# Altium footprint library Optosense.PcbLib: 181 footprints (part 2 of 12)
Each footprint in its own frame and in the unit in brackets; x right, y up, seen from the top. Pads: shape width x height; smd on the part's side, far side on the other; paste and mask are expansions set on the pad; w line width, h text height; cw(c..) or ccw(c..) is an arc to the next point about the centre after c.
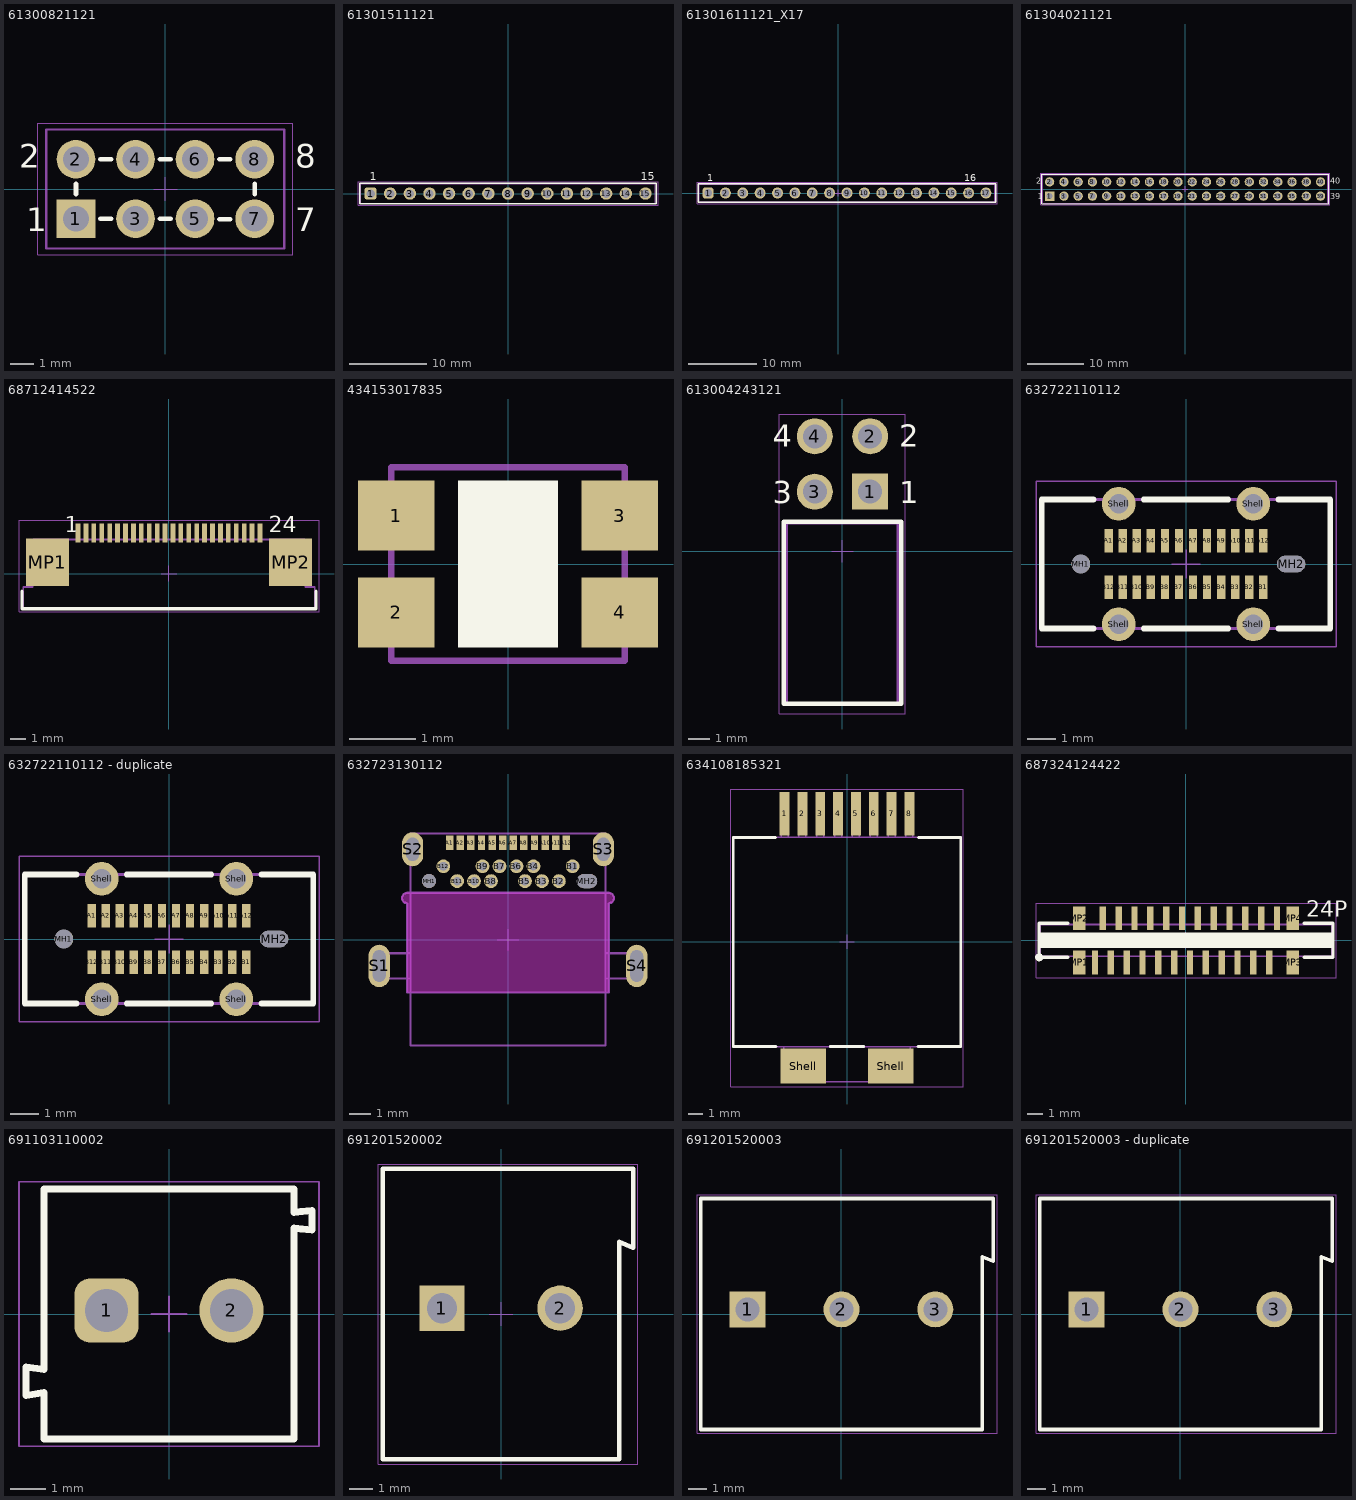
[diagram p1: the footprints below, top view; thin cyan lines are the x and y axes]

## 61300821121 [mm] "Pin Header, pitch 2.54 mm, THT, Vertical, dual row, 8p"
height 8.54
pads (8):
  rect 1.65x1.65 hole 1.1: 1(-3.81,-1.27)
  round 1.65 hole 1.1: 2(-3.81,1.27) 3(-1.27,-1.27) 4(-1.27,1.27) 5(1.27,-1.27) 6(1.27,1.27) 7(3.81,-1.27) 8(3.81,1.27)
Top Overlay:
  lines w0.2: -3.81,-0.229 -3.81,0.229 ; -2.769,-1.27 -2.311,-1.27 ; -2.769,1.27 -2.311,1.27 ; -0.229,-1.27 0.229,-1.27 ; -0.229,1.27 0.229,1.27 ; 2.311,-1.295 2.769,-1.295 ; 2.311,1.27 2.769,1.27 ; 3.81,-0.229 3.81,0.229
  text "8" at 5.54,0.9 h1.02
  text "7" at 5.54,-1.8 h1.02
  text "2" at -6.24,0.9 h1.02
  text "1" at -5.94,-1.8 h1.02
Mechanical 13:
  lines w0.1: -5.08,-2.54 5.08,-2.54 5.08,2.54 -5.08,2.54 -5.08,-2.54
Mechanical 15:
  lines w0.05: -0.5,0 0.5,0 ; 0,-0.5 0,0.5 ; -5.43,-2.815 -5.43,2.815 5.43,2.815 5.43,-2.815 -5.43,-2.815
3D body "61300821121.stp": height 8.59, standoff -2.95, extent -5.08,-2.54 5.08,2.54

## 61301511121 [mm] "Pin Header, pitch 2.54 mm, THT, Vertical, single row, 15p"
height 8.54
pads (15):
  rrect50% 1.6x1.6 hole 1.1: 1(-17.78,0)
  round 1.6 hole 1.1: 2(-15.24,0) 3(-12.7,0) 4(-10.16,0) 5(-7.62,0) 6(-5.08,0) 7(-2.54,0) 8(0,0) 9(2.54,0) 10(5.08,0) 11(7.62,0) 12(10.16,0) 13(12.7,0) 14(15.24,0) 15(17.78,0)
Top Overlay:
  lines w0.2: -19.2,-1.345 19.2,-1.345 19.2,1.345 -19.2,1.345 -19.2,-1.345
  text "15" at 17.15,1.7 h1.02
  text "1" at -17.9,1.7 h1.02
Top 3D Body:
  lines w0.1: -19.05,-1.27 -19.05,1.27 19.05,1.27 19.05,-1.27 -19.05,-1.27
Top Courtyard:
  lines w0.05: -0.5,0 0.5,0 ; 0,-0.5 0,0.5 ; -19.4,-1.545 -19.4,1.545 19.4,1.545 19.4,-1.545 -19.4,-1.545
Top Assembly:
  lines w0.1: -19.05,-1.27 -19.05,1.27 19.05,1.27 19.05,-1.27 -19.05,-1.27
  text ".Designator" at -7.498,-0.5 h1.5
3D body "61301511121.stp": height 8.57, standoff -2.97, extent -19.05,-1.27 19.05,1.27

## 61301611121_X17 [mm] "Pin Header, pitch 2.54 mm, THT, Vertical, single row, 16p"
height 8.54
pads (17):
  rrect50% 1.6x1.6 hole 1.1: 1(-19.05,0)
  round 1.6 hole 1.1: 2(-16.51,0) 3(-13.97,0) 4(-11.43,0) 5(-8.89,0) 6(-6.35,0) 7(-3.81,0) 8(-1.27,0) 9(1.27,0) 10(3.81,0) 11(6.35,0) 12(8.89,0) 13(11.43,0) 14(13.97,0) 15(16.51,0) 16(19.05,0) 17(21.59,0)
Top Overlay:
  lines w0.2: -20.47,-1.345 -20.47,1.345 23.01,1.345 23.01,-1.345 -20.47,-1.345
  text "16" at 18.42,1.7 h1.02
  text "1" at -19.17,1.7 h1.02
Top 3D Body:
  lines w0.1: 20.32,-1.27 -20.32,-1.27 -20.32,1.27 20.32,1.27 ; 22.86,-1.27 22.86,1.27
Top Courtyard:
  lines w0.05: -0.5,0 0.5,0 ; 0,-0.5 0,0.5 ; -20.67,-1.545 23.21,-1.545 23.21,1.545 -20.67,1.545 -20.67,-1.545
Top Assembly:
  lines w0.1: -20.32,-1.27 22.86,-1.27 22.86,1.27 -20.32,1.27 -20.32,-1.27
  text ".Designator" at -7.498,-0.5 h1.5
3D body "61301611121.stp": height 8.57, standoff -2.97, extent -17.78,-1.27 22.86,1.27
3D body "61301611121.stp": height 8.57, standoff -2.97, extent -20.32,-1.27 20.32,1.27

## 61304021121 [mm] "Pin Header, pitch 2.54 mm, THT, Vertical, dual row, 40p"
height 8.54
pads (40):
  rect 1.65x1.65 hole 1.1: 1(-24.13,-1.27)
  round 1.65 hole 1.1: 2(-24.13,1.27) 3(-21.59,-1.27) 4(-21.59,1.27) 5(-19.05,-1.27) 6(-19.05,1.27) 7(-16.51,-1.27) 8(-16.51,1.27) 9(-13.97,-1.27) 10(-13.97,1.27) 11(-11.43,-1.27) 12(-11.43,1.27) 13(-8.89,-1.27) 14(-8.89,1.27) 15(-6.35,-1.27) 16(-6.35,1.27) 17(-3.81,-1.27) 18(-3.81,1.27) 19(-1.27,-1.27) 20(-1.27,1.27) 21(1.27,-1.27) 22(1.27,1.27) 23(3.81,-1.27) 24(3.81,1.27) 25(6.35,-1.27) 26(6.35,1.27) 27(8.89,-1.27) 28(8.89,1.27) 29(11.43,-1.27) 30(11.43,1.27) 31(13.97,-1.27) 32(13.97,1.27) 33(16.51,-1.27) 34(16.51,1.27) 35(19.05,-1.27) 36(19.05,1.27) 37(21.59,-1.27) 38(21.59,1.27) 39(24.13,-1.27) 40(24.13,1.27)
Top Overlay:
  lines w0.2: -25.55,-2.615 -25.55,2.615 25.55,2.615 25.55,-2.615 -25.55,-2.615
  text "40" at 25.86,0.9 h1.02
  text "39" at 25.86,-1.8 h1.02
  text "1" at -26.26,-1.8 h1.02
  text "2" at -26.56,0.9 h1.02
Mechanical 13:
  lines w0.1: -25.4,-2.54 -25.4,2.54 25.4,2.54 25.4,-2.54 -25.4,-2.54
Mechanical 15:
  lines w0.05: -0.5,0 0.5,0 ; 0,-0.5 0,0.5 ; -25.75,-2.815 25.75,-2.815 25.75,2.815 -25.75,2.815 -25.75,-2.815
3D body "61304021121.stp": height 8.59, standoff -2.95, extent -25.4,-2.54 25.4,2.54

## 68712414522 [mm] "ZIF Connectors, Horizontal, Bottom Contact, pitch 0.5mm, 24p"
height 2.25
pads (26):
  rect 0.3x1.2 smd: 1(-5.75,2.56) 2(-5.25,2.56) 3(-4.75,2.56) 4(-4.25,2.56) 5(-3.75,2.56) 6(-3.25,2.56) 7(-2.75,2.56) 8(-2.25,2.56) 9(-1.75,2.56) 10(-1.25,2.56) 11(-0.75,2.56) 12(-0.25,2.56) 13(0.25,2.56) 14(0.75,2.56) 15(1.25,2.56) 16(1.75,2.56) 17(2.25,2.56) 18(2.75,2.56) 19(3.25,2.56) 20(3.75,2.56) 21(4.25,2.56) 22(4.75,2.56) 23(5.25,2.56) 24(5.75,2.56)
  rect 2.7x3 smd: MP1(-7.68,0.7) MP2(7.68,0.7)
Top Overlay:
  lines w0.2: -9.275,-1.125 -9.275,-2.225 9.275,-2.225 9.275,-1.125
  text "24" at 6.3,2.61 h1.02
  text "1" at -6.6,2.61 h1.02
Mechanical 13:
  lines w0.1: -9.2,-2.15 -9.2,-0.85 -8.6,-0.85 -8.6,2.15 8.6,2.15 8.6,-0.85 9.2,-0.85 9.2,-2.15 -9.2,-2.15
Mechanical 15:
  lines w0.05: -0.5,0 0.5,0 ; 0,-0.5 0,0.5 ; -9.475,-2.425 9.475,-2.425 9.475,3.36 -9.475,3.36 -9.475,-2.425
3D body "68712414522.stp": height 2.1, standoff 0, extent -9.2,-2.15 9.2,2.95

## 434153017835 [mm] "Tact Switch, SMD, body 3.5x2.9mm"
height 1.7
pads (4):
  rect 1.15x1.05 smd: 1(-1.675,0.725) 2(-1.675,-0.725) 3(1.675,0.725) 4(1.675,-0.725)
Top Overlay:
  rectangle: -0.75,-1.25 0.75,1.25
Mechanical 11:
  lines w0.1: -1.75,-1.45 -1.75,1.45 1.75,1.45 1.75,-1.45 -1.75,-1.45
  text ".Designator" at -1.4,-0.6 h1.2
Mechanical 13:
  lines w0.1: -1.75,-1.45 1.75,-1.45 1.75,1.45 -1.75,1.45 -1.75,-1.45
Mechanical 15:
  lines w0.05: -0.5,0 0.5,0 ; 0,-0.5 0,0.5
3D body "434153017835.stp": height 1.7, standoff 0, extent -2.147,-1.45 2.147,1.45

## 613004243121 [mm]
height 5.08
pads (4):
  rect 1.65x1.65 hole 1.1: 1(1.27,2.73)
  round 1.65 hole 1.1: 2(1.27,5.27) 3(-1.27,2.73) 4(-1.27,5.27)
Top Overlay:
  lines w0.2: -2.69,-7 -2.69,1.345 2.69,1.345 2.69,-7 -2.69,-7
  text "1" at 2.6,2.2 h1.02
  text "2" at 2.6,4.8 h1.02
  text "4" at -3.2,4.8 h1.02
  text "3" at -3.2,2.2 h1.02
Mechanical 13:
  lines w0.1: -2.54,-7 2.54,-7 2.54,1.27 -2.54,1.27 -2.54,-7
Mechanical 15:
  lines w0.05: -0.5,0 0.5,0 ; 0,-0.5 0,0.5 ; -2.89,-7.47 -2.89,6.295 2.89,6.295 2.89,-7.47 -2.89,-7.47
3D body "613004243121.stp": height 5.05, standoff -3.25, extent -2.79,-7.1 2.79,5.5

## 632722110112 [mm] "USB_Type C 3.1_Vertical_SMT_1,0mm"
height 7.6
pads (30):
  rect 0.3x0.85 smd: A1(-2.75,0.83) A2(-2.25,0.83) A3(-1.75,0.83) A4(-1.25,0.83) A5(-0.75,0.83) A6(-0.25,0.83) A7(0.25,0.83) A8(0.75,0.83) A9(1.25,0.83) A10(1.75,0.83) A11(2.25,0.83) A12(2.75,0.83) B1(2.75,-0.83) B2(2.25,-0.83) B3(1.75,-0.83) B4(1.25,-0.83) B5(0.75,-0.83) B6(0.25,-0.83) B7(-0.25,-0.83) B8(-0.75,-0.83) B9(-1.25,-0.83) B10(-1.75,-0.83) B11(-2.25,-0.83) B12(-2.75,-0.83)
  round 0.66 hole 0.66 unplated: MH1(-3.75,0)
  oval 1x0.58 hole 0.58 slot 1 at 0 deg unplated: MH2(3.75,0)
  round 1.2 hole 0.7: Shell(-2.4,-2.15) Shell(-2.4,2.15) Shell(2.4,-2.15) Shell(2.4,2.15)
Top Overlay:
  lines w0.2: -3.3,-2.3 -5.15,-2.3 -5.15,2.3 -3.3,2.3 ; -1.5,-2.3 1.5,-2.3 ; -1.5,2.3 1.5,2.3 ; 3.3,-2.3 5.15,-2.3 5.15,2.3 3.3,2.3
Mechanical 11:
  lines w0.1: -5.15,-2.3 5.15,-2.3 5.15,2.3 -5.15,2.3 -5.15,-2.3
  text ".Designator" at -1.75,-0.75 h1.5
Mechanical 13:
  lines w0.1: -5.15,-2.3 -5.15,2.3 5.15,2.3 5.15,-2.3 -5.15,-2.3
Mechanical 15:
  lines w0.05: -0.5,0 0.5,0 ; 0,-0.5 0,0.5 ; -5.35,-2.95 -5.35,2.95 5.35,2.95 5.35,-2.95 -5.35,-2.95
3D body "632722110112.stp": height 7.95, standoff -1.32, extent -5.15,-2.3 5.15,2.3

## 632722110112 - duplicate [mm] "USB_Type C 3.1_Vertical_SMT_1,0mm"
height 7.6
pads (30):
  rect 0.3x0.85 smd: A1(-2.75,0.83) A2(-2.25,0.83) A3(-1.75,0.83) A4(-1.25,0.83) A5(-0.75,0.83) A6(-0.25,0.83) A7(0.25,0.83) A8(0.75,0.83) A9(1.25,0.83) A10(1.75,0.83) A11(2.25,0.83) A12(2.75,0.83) B1(2.75,-0.83) B2(2.25,-0.83) B3(1.75,-0.83) B4(1.25,-0.83) B5(0.75,-0.83) B6(0.25,-0.83) B7(-0.25,-0.83) B8(-0.75,-0.83) B9(-1.25,-0.83) B10(-1.75,-0.83) B11(-2.25,-0.83) B12(-2.75,-0.83)
  round 0.66 hole 0.66 unplated: MH1(-3.75,0)
  oval 1x0.58 hole 0.58 slot 1 at 0 deg unplated: MH2(3.75,0)
  round 1.2 hole 0.7: Shell(-2.4,-2.15) Shell(-2.4,2.15) Shell(2.4,-2.15) Shell(2.4,2.15)
Top Overlay:
  lines w0.2: -3.3,-2.3 -5.15,-2.3 -5.15,2.3 -3.3,2.3 ; -1.5,-2.3 1.5,-2.3 ; -1.5,2.3 1.5,2.3 ; 3.3,-2.3 5.15,-2.3 5.15,2.3 3.3,2.3
Top 3D Body:
  lines w0.1: -5.15,-2.3 5.15,-2.3 5.15,2.3 -5.15,2.3 -5.15,-2.3
Top Courtyard:
  lines w0.05: -0.5,0 0.5,0 ; 0,-0.5 0,0.5 ; -5.35,-2.95 5.35,-2.95 5.35,2.95 -5.35,2.95 -5.35,-2.95
Top Component Outline:
  lines w0.1: -5.15,-2.3 -5.15,2.3 5.15,2.3 5.15,-2.3 -5.15,-2.3
Top Designator:
  text ".Designator" at -7.498,-0.5 h1.5
3D body "632722110112.stp": height 7.95, standoff -1.32, extent -5.15,-2.3 5.15,2.3

## 632723130112 [mm] "USB_Type C 3.1_Mid-Mount_THR/SMT_1,6mm"
height 3.42
pads (30):
  rect 0.35x0.7 smd: A1(-2.75,4.57) A2(-2.25,4.57) A3(-1.75,4.57) A4(-1.25,4.57) A5(-0.75,4.57) A6(-0.25,4.57) A7(0.25,4.57) A8(0.75,4.57) A9(1.25,4.57) A10(1.75,4.57) A11(2.25,4.57) A12(2.75,4.57)
  round 0.65 hole 0.4: B1(3.05,3.46) B2(2.4,2.76) B3(1.6,2.76) B4(1.2,3.46) B5(0.8,2.76) B6(0.4,3.46) B7(-0.4,3.46) B8(-0.8,2.76) B9(-1.2,3.46) B10(-1.6,2.76) B11(-2.4,2.76) B12(-3.05,3.46)
  round 0.65 hole 0.65 unplated: MH1(-3.725,2.76)
  oval 0.95x0.65 hole 0.65 slot 0.95 at 0 deg unplated: MH2(3.725,2.76)
  oval 1x2 hole 0.6 slot 1.5 at 90 deg: S1(-6.075,-1.24) S4(6.075,-1.24)
  oval 1x1.6 hole 0.6 slot 1.1 at 90 deg: S2(-4.5,4.26) S3(4.5,4.26)
Keep-Out Layer:
  board cut-out: -4.75,-2.49 4.75,-2.49 4.75,1.71 4.8,1.71 4.892,1.748 4.962,1.818 5,1.91 5,2.01 4.962,2.102 4.892,2.172 4.8,2.21 4.75,2.21 -4.75,2.21 -4.8,2.21 -4.892,2.172 -4.962,2.102 -5,2.01 -5,1.91 -4.962,1.818 -4.892,1.748 -4.8,1.71 -4.75,1.71
Mechanical 2:
  lines w0.1: -4.75,-2.49 4.75,-2.49
  text "PCB End" at -1.85,-3.39 h1.02
Mechanical 8:
  lines w0.1: -4.75,-2.49 4.75,-2.49 4.75,1.71 ccw(c4.75,1.96) 4.75,2.21 -4.75,2.21 ccw(c-4.75,1.96) -4.75,1.71 -4.75,-2.49
  text "Milling Area" at -2.2,-0.34 h1.02
Mechanical 13:
  lines w0.1: -4.6,-1.84 -6.175,-1.84 -6.175,-0.64 -4.6,-0.64 ; 4.6,-1.84 6.175,-1.84 6.175,-0.64 4.6,-0.64 ; -4.6,-5 4.6,-5 4.6,5 -4.6,5 -4.6,-5
Mechanical 15:
  lines w0.05: -0.5,0 0.5,0 ; 0,-0.5 0,0.5
3D body "632723130112.stp": height 2.04, standoff -1.56, extent -6.175,-5 6.175,4.994

## 634108185321 [mm] "Modular Jack Vertical Shielded SMT  with Solder Tab 8P8C Top Entry"
height 13.3
pads (10):
  rect 0.7x3.1 smd: 1(-4.445,9.15) 2(-3.175,9.15) 3(-1.905,9.15) 4(-0.635,9.15) 5(0.635,9.15) 6(1.905,9.15) 7(3.175,9.15) 8(4.445,9.15)
  rect 3.25x2.5 smd: Shell(-3.125,-8.85) Shell(3.125,-8.85)
Top Overlay:
  lines w0.2: -5.1,7.45 -8.1,7.45 -8.1,-7.45 -5.05,-7.45 ; -1.2,-7.45 1.2,-7.45 ; 5.05,-7.45 8.1,-7.45 8.1,7.45 5.1,7.45
Top 3D Body:
  lines w0.1: -4.695,7.45 -4.695,9.1 -4.195,9.1 -4.195,7.45 ; -4.5,-7.45 -4.5,-9.95 4.5,-9.95 4.5,-7.45 ; -3.425,7.45 -3.425,9.1 -2.925,9.1 -2.925,7.45 ; -2.155,7.45 -2.155,9.1 -1.655,9.1 -1.655,7.45 ; -0.885,7.45 -0.885,9.1 -0.385,9.1 -0.385,7.45 ; 0.385,7.45 0.385,9.1 0.885,9.1 0.885,7.45 ; 1.655,7.45 1.655,9.1 2.155,9.1 2.155,7.45 ; 2.925,7.45 2.925,9.1 3.425,9.1 3.425,7.45 ; 4.195,7.45 4.195,9.1 4.695,9.1 4.695,7.45 ; -8.1,-7.45 -8.1,7.45 8.1,7.45 8.1,-7.45 -8.1,-7.45
Top Courtyard:
  lines w0.05: -0.5,0 0.5,0 ; 0,-0.5 0,0.5 ; -8.3,-10.3 8.3,-10.3 8.3,10.9 -8.3,10.9 -8.3,-10.3
Top Assembly:
  lines w0.1: -4.695,7.45 -4.695,9.1 -4.195,9.1 -4.195,7.45 ; -4.5,-7.45 -4.5,-9.95 4.5,-9.95 4.5,-7.45 ; -3.425,7.45 -3.425,9.1 -2.925,9.1 -2.925,7.45 ; -2.155,7.45 -2.155,9.1 -1.655,9.1 -1.655,7.45 ; -0.885,7.45 -0.885,9.1 -0.385,9.1 -0.385,7.45 ; 0.385,7.45 0.385,9.1 0.885,9.1 0.885,7.45 ; 1.655,7.45 1.655,9.1 2.155,9.1 2.155,7.45 ; 2.925,7.45 2.925,9.1 3.425,9.1 3.425,7.45 ; 4.195,7.45 4.195,9.1 4.695,9.1 4.695,7.45 ; -8.1,-7.45 8.1,-7.45 8.1,7.45 -8.1,7.45 -8.1,-7.45
  text ".Designator" at -7.498,-0.5 h1.5
3D body "634108185321.stp": height 13.48, standoff 0.02, extent -8.16,-9.95 8.16,9.107

## 687324124422 [mm] "ZIF Connectors, Vertical, Type A, pitch 0.5mm, 24p"
height 4.5
pads (28):
  rect 0.4x1.5 smd: 1(-5.75,-1.4) 2(-5.25,1.4) 3(-4.75,-1.4) 4(-4.25,1.4) 5(-3.75,-1.4) 6(-3.25,1.4) 7(-2.75,-1.4) 8(-2.25,1.4) 9(-1.75,-1.4) 10(-1.25,1.4) 11(-0.75,-1.4) 12(-0.25,1.4) 13(0.25,-1.4) 14(0.75,1.4) 15(1.25,-1.4) 16(1.75,1.4) 17(2.25,-1.4) 18(2.75,1.4) 19(3.25,-1.4) 20(3.75,1.4) 21(4.25,-1.4) 22(4.75,1.4) 23(5.25,-1.4) 24(5.75,1.4)
  rect 0.8x1.5 smd: MP1(-6.75,-1.4) MP2(-6.75,1.4) MP3(6.75,-1.4) MP4(6.75,1.4)
Top Overlay:
  circle w0.25: c-9.275,-1.075 r0.125
  rectangle: -9.275,-0.5 9.275,0.5
  lines w0.2: -7.45,-1.075 -9.275,-1.075 -9.275,1.075 -7.45,1.075 ; 7.45,-1.075 9.275,-1.075 9.275,1.075 7.45,1.075
  text "24P" at 7.6,1.5 h1.02
Mechanical 13:
  lines w0.1: -9.2,-1 -9.2,1 9.2,1 9.2,-1 -9.2,-1
Mechanical 15:
  lines w0.05: -0.5,0 0.5,0 ; 0,-0.5 0,0.5 ; -9.475,-2.35 -9.475,2.35 9.475,2.35 9.475,-2.35 -9.475,-2.35
3D body "687324124422.stp": height 4.92, standoff 0.02, extent -9.2,-1.75 9.2,1.75

## 691103110002 [mm] "3,50mm - modular - blue - Horizontal wire entry - Pressure clamp - 8,4mm height - 02p"
height 8.4
pads (2):
  rrect50% 1.8x1.8 hole 1.2: 1(-1.75,0.1)
  round 1.8 hole 1.2: 2(1.75,0.1)
Top Overlay:
  lines w0.2: -3.5,-1.55 -3.5,3.5 3.5,3.5 3.5,2.85 4,2.899 4,2.35 ; -3.499,-1.55 -4,-1.48 -4,-2.278 -3.5,-2.2 -3.5,-3.5 3.5,-3.5 3.5,2.4 4,2.351
Mechanical 11:
  lines w0.1: -3.5,-1.55 -3.5,3.5 3.5,3.5 3.5,2.85 4,2.899 4,2.35 ; -3.499,-1.55 -4,-1.48 -4,-2.278 -3.5,-2.2 -3.5,-3.5 3.5,-3.5 3.5,2.4 4,2.351
  text ".Designator" at -1.75,-0.75 h1.5
Mechanical 13:
  lines w0.1: -3.5,-1.55 -3.5,3.5 3.5,3.5 3.5,2.85 4,2.899 4,2.35 ; -3.499,-1.55 -4,-1.48 -4,-2.278 -3.5,-2.2 -3.5,-3.5 3.5,-3.5 3.5,2.4 4,2.351
Mechanical 15:
  lines w0.05: -0.5,0 0.5,0 ; 0,-0.5 0,0.5 ; -4.2,-3.7 -4.2,3.7 4.2,3.7 4.2,-3.7 -4.2,-3.7
3D body "691103110002.stp": height 8.45, standoff -3.75, extent -4,-3.5 4,3.5

## 691201520002 [mm] "Serie 2015 - 5.08 mm _ 2 pins"
height 12
pads (2):
  rect 1.95x1.95 hole 1.3: 1(-2.54,0.25)
  round 1.95 hole 1.3: 2(2.54,0.25)
Top Overlay:
  lines w0.2: -5.08,-6.25 5.08,-6.25 5.08,3.1 5.68,2.85 5.68,6.25 -5.08,6.25 -5.08,-6.25
Mechanical 13:
  lines w0.1: -5.08,-6.25 -5.08,6.25 5.68,6.25 5.68,2.85 5.08,3.1 5.08,-6.25 -5.08,-6.25
Mechanical 15:
  lines w0.05: -0.5,0 0.5,0 ; 0,-0.5 0,0.5 ; -5.28,-6.45 -5.28,6.45 5.88,6.45 5.88,-6.45 -5.28,-6.45
3D body "691201520002.stp": height 12.1, standoff -4.4, extent -5.08,-6.25 5.68,6.25

## 691201520003 [mm] "Serie 2015 - 5.08 mm _ 3 pins"
height 12
pads (3):
  rect 1.95x1.95 hole 1.3: 1(-5.08,0.25)
  round 1.95 hole 1.3: 2(0,0.25) 3(5.08,0.25)
Top Overlay:
  lines w0.2: -7.62,-6.25 -7.62,6.25 8.22,6.25 8.22,2.85 7.62,3.1 7.62,-6.25 -7.62,-6.25
Mechanical 13:
  lines w0.1: -7.62,-6.25 7.62,-6.25 7.62,3.1 8.22,2.85 8.22,6.25 -7.62,6.25 -7.62,-6.25
Mechanical 15:
  lines w0.05: -0.5,0 0.5,0 ; 0,-0.5 0,0.5 ; -7.82,-6.45 8.42,-6.45 8.42,6.45 -7.82,6.45 -7.82,-6.45
3D body "691201520003.stp": height 12.1, standoff -4.4, extent -7.62,-6.25 8.22,6.25

## 691201520003 - duplicate [mm] "Serie 2015 - 5.08 mm _ 3 pins"
height 12
pads (3):
  rect 1.95x1.95 hole 1.3: 1(-5.08,0.25)
  round 1.95 hole 1.3: 2(0,0.25) 3(5.08,0.25)
Top Overlay:
  lines w0.2: -7.62,-6.25 7.62,-6.25 7.62,3.1 8.22,2.85 8.22,6.25 -7.62,6.25 -7.62,-6.25
Mechanical 13:
  lines w0.1: -7.62,-6.25 -7.62,6.25 8.22,6.25 8.22,2.85 7.62,3.1 7.62,-6.25 -7.62,-6.25
Mechanical 15:
  lines w0.05: -0.5,0 0.5,0 ; 0,-0.5 0,0.5 ; -7.82,-6.45 -7.82,6.45 8.42,6.45 8.42,-6.45 -7.82,-6.45
3D body "691201520003.stp": height 12.1, standoff -4.4, extent -7.62,-6.25 8.22,6.25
